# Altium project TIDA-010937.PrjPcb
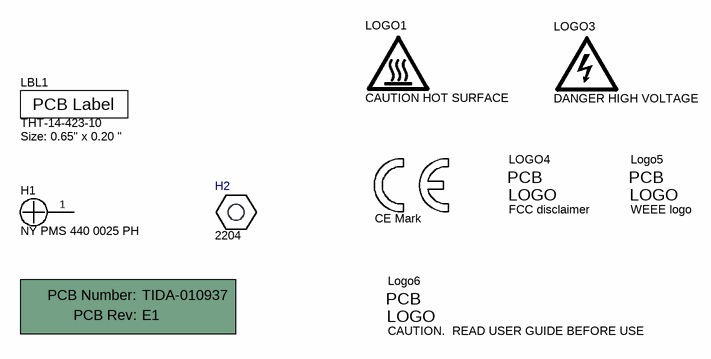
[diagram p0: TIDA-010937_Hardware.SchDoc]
TID: N/A; TechSupport: http://www.ti.com/support; SCH_Rev: E1; PRJ_Title: TMCS1123 isolated current sensing; PRJ_Number: TIDA-010937; PRJ_Engineer: Yufeng/Martin; PRJ_Customer: Public Release; PCB_Rev: E1; PCB_Layout: Yufeng; CopyrightYear: 2023
2 sheets, 91 parts. Net scope: flat (ports and power ports of the same name join across sheets).
Board file: TIDA-010937_PCB.PcbDoc
Sheets:
  TIDA-010937_Hardware.SchDoc
  TIDA-010937_SCH.SchDoc

## Sheet TIDA-010937_Hardware.SchDoc
size 431 x 279 mm; Date: Not shown in title block; ApprovedBy: Not shown in title block; CheckedBy: Not shown in title block; Author: Not shown in title block; CompanyName: Not shown in title block; Engineer: Not shown in title block; Organization: Not shown in title block; Address1: Not shown in title block; Address2: Not shown in title block; Address3: Not shown in title block; Address4: Not shown in title block; DocumentNumber: 3; Revision: Use project parameter SCH_Rev; SheetNumber: 2; SheetTotal: 3; PageSetup: Record=PageOptions¦CenterHorizontal=True¦CenterVertical=True¦PrintScale=1.00¦XCorrection=1.00¦YCorrection=1.00¦PrintKind=0¦BorderSize=5000000¦LeftOffset=0¦BottomOffset=0¦Orientation=2¦PaperLength=1000¦PaperWidth=1000¦Scale=100¦PaperSource=15¦PrintQuality=600¦MediaType=1¦DitherType=10¦PaperKind=Letter¦PrintScaleMode=1

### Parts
!PCB1  Printed Circuit Board  (value not drawn)  (mechanical)
H1  NY PMS 440 0025 PH  [NY PMS 440 0025 PH]
H2  2204  [Keystone_2204]
LBL1  THT-14-423-10  Note: Size: 0.65" x 0.20 "  [Label_650x200]
LOGO1  CAUTION HOT SURFACE  [IEC_HotSurface_Medium]  (no BOM)
Logo2  CE Mark  [CE_Mark_5mm]  (no BOM)
LOGO3  DANGER HIGH VOLTAGE  [IEC_HighVoltage_Medium]  (no BOM)
LOGO4  FCC disclaimer  [FCC_disclaimer]  (no BOM)
Logo5  WEEE logo  [WEEE_Minimum]  (no BOM)
Logo6  CAUTION.  READ USER GUIDE BEFORE USE  [IEC_Caution_Small]  (no BOM)

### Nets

Not connected (* = marked no-connect by the designer): H1 1

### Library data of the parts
!PCB1 = CMP-0003618-2: Manufacturer: Any; PartNumber: TIDA-010937
H1 = CMP-0003617-1: Machine Screw, Round, #4-40 x 1/4, Nylon, Philips panhead; Manufacturer: B&F Fastener Supply; CompType: Hardware
H2 = CMP-0003917-1: Manufacturer: Keystone; CompType: Standoff
LBL1 = CMP-0003625-1: Thermal Transfer Printable Labels, 0.650" W x 0.200" H - 10,000 per roll; Manufacturer: Brady; CompType: Label
LOGO1 = CMP-0074837-1: IEC 61010-1 Hot Surface Warning; SymbolCreator: a0412235
Logo2 = CMP-0074844-1: SymbolCreator: a0412235
LOGO3 = CMP-0074835-1: IEC 61010-1 High Voltage Warning; SymbolCreator: a0412235
LOGO4 = CMP-0074847-1: FCC_disclaimer; Library Reference: Logo
Logo5 = CMP-0074769-1
Logo6 = CMP-0074836-1: IEC 61010-1 Caution Warning; SymbolCreator: a0412235; Lib Reference: IEC_Caution

## Sheet TIDA-010937_SCH.SchDoc
size 431 x 279 mm; Date: Not shown in title block; ApprovedBy: Not shown in title block; CheckedBy: Not shown in title block; Author: Not shown in title block; CompanyName: Not shown in title block; Engineer: Not shown in title block; Organization: Not shown in title block; Address1: Not shown in title block; Address2: Not shown in title block; Address3: Not shown in title block; Address4: Not shown in title block; DocumentNumber: 2; Revision: Use project parameter SCH_Rev; SheetNumber: 2; SheetTotal: 2; PageSetup: Record=PageOptions¦CenterHorizontal=True¦CenterVertical=True¦PrintScale=1.00¦XCorrection=1.00¦YCorrection=1.00¦PrintKind=0¦BorderSize=5000000¦LeftOffset=0¦BottomOffset=0¦Orientation=2¦PaperLength=1000¦PaperWidth=1000¦Scale=100¦PaperSource=15¦PrintQuality=600¦MediaType=1¦DitherType=10¦PaperKind=Letter¦PrintScaleMode=1
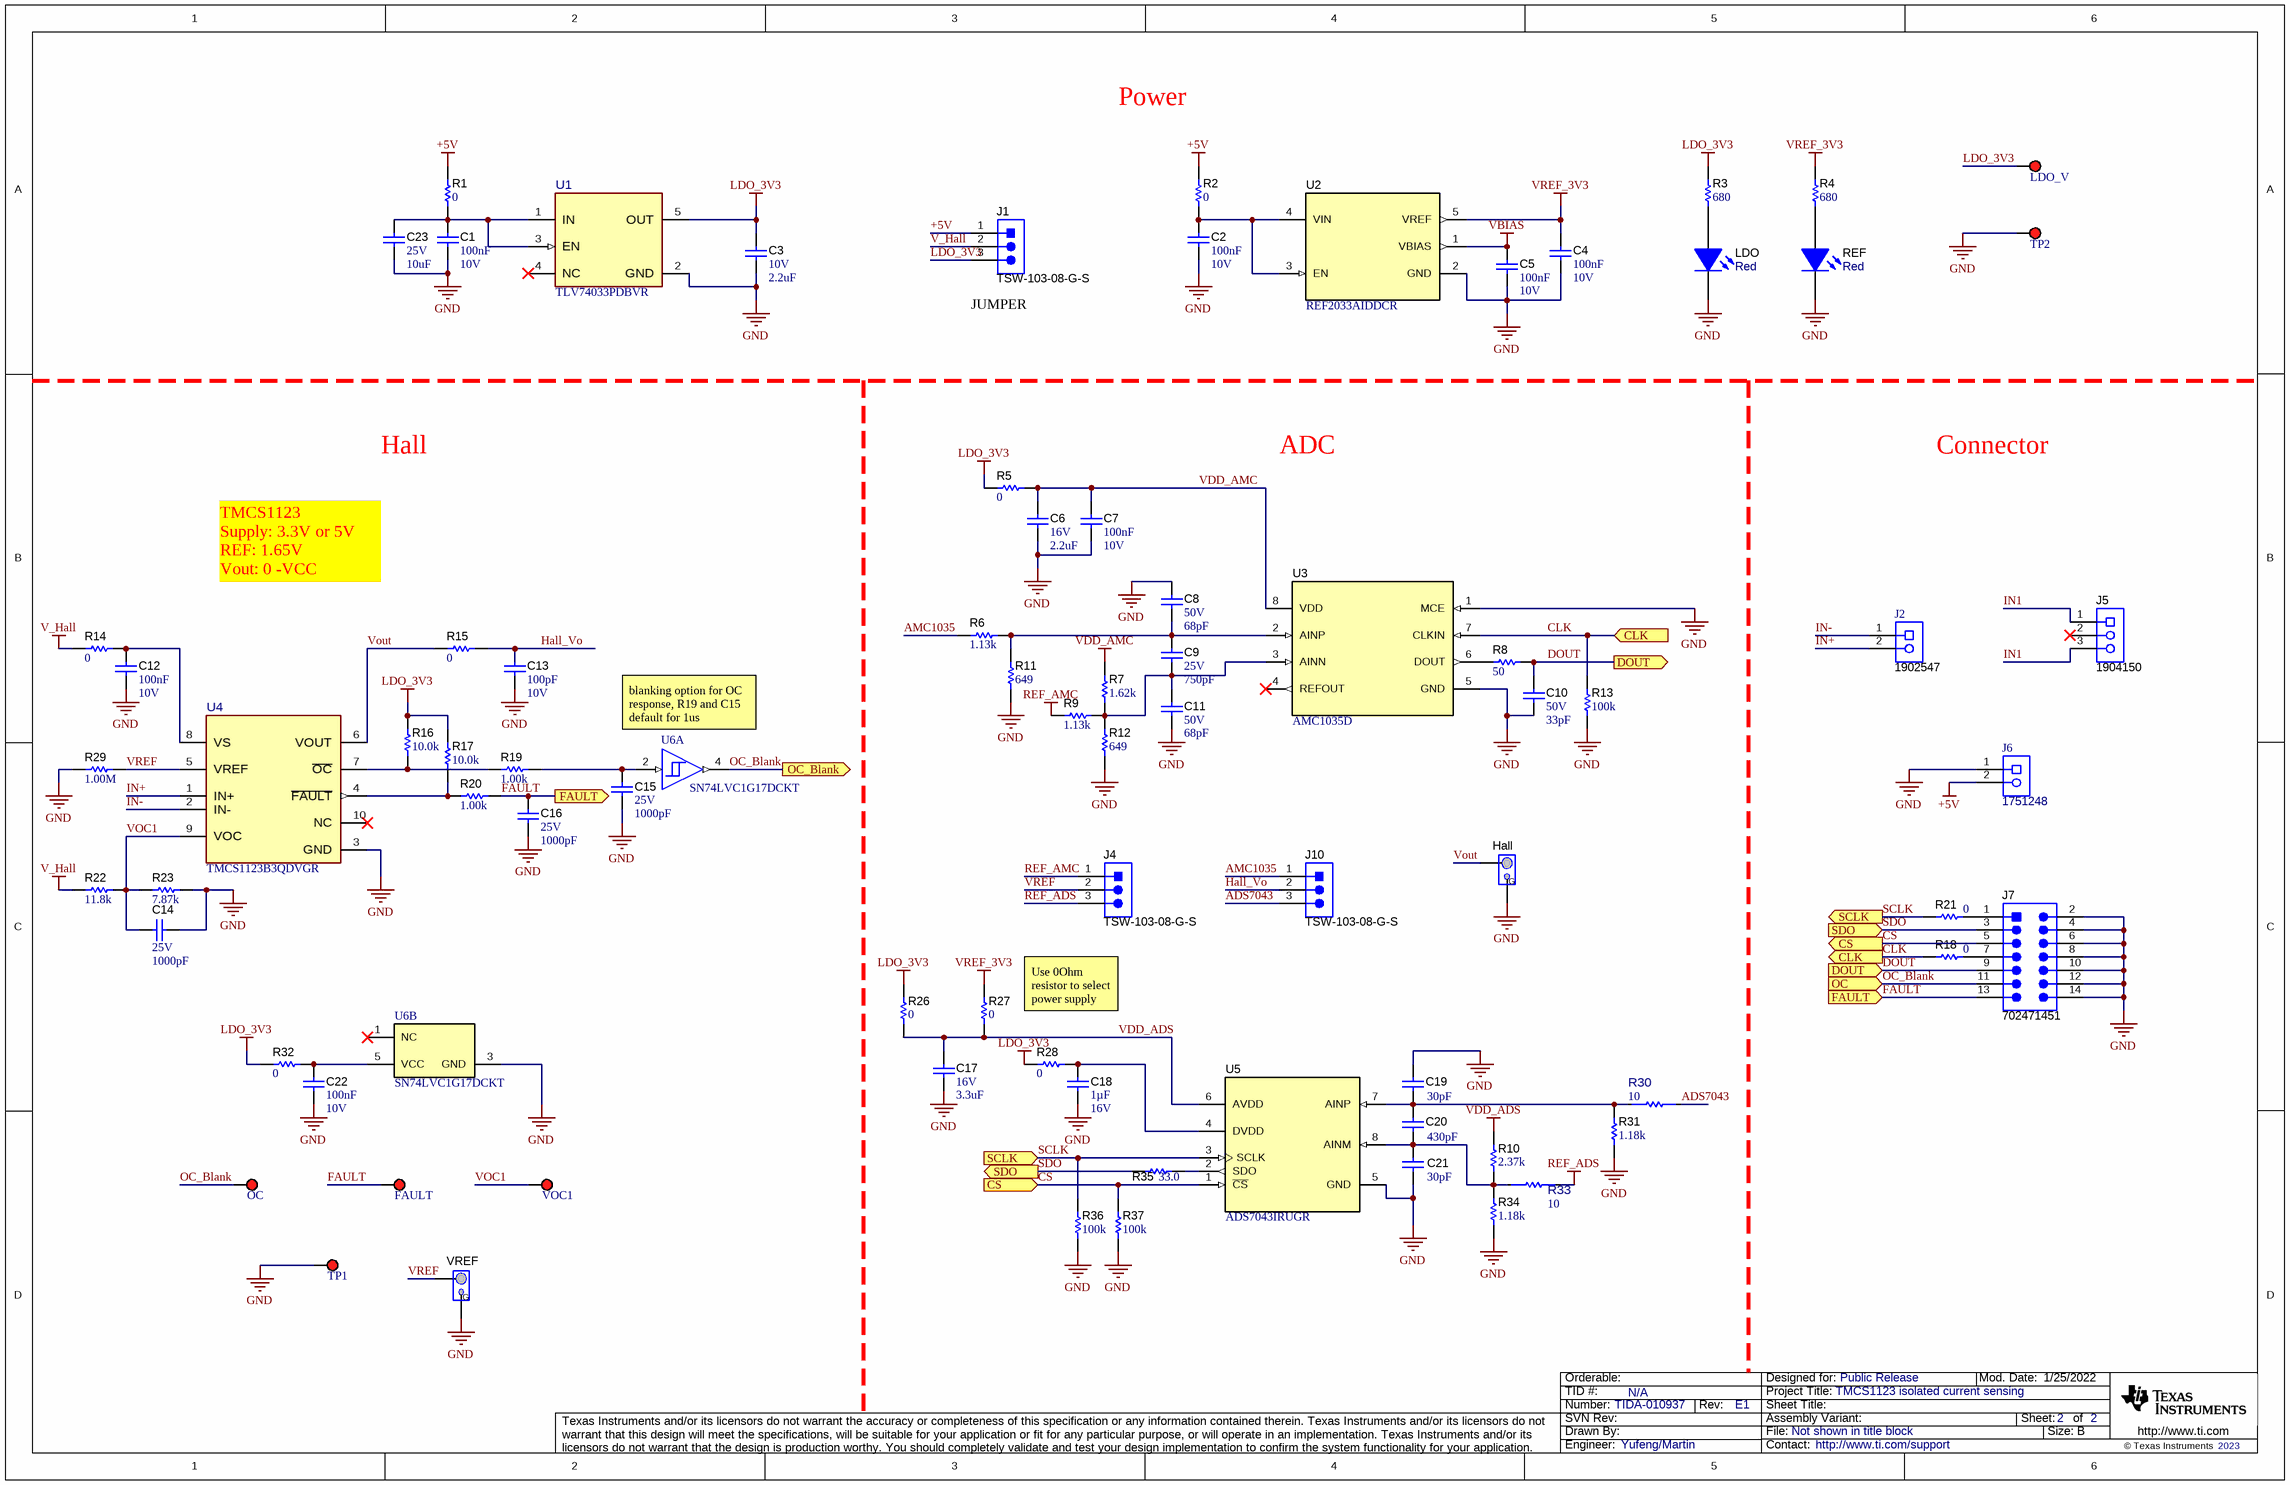
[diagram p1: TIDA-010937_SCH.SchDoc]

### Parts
C1  Cap_F: 100nF  VDC_V: 10V  [0603]  (hidden comment: C0603C104K8RACTU)
C2  Cap_F: 100nF  VDC_V: 10V  [0603]  (hidden comment: C0603C104K8RACTU)
C3  VDC_V: 10V  ValueDisplayed: 2.2uF  [0603]  (hidden comment: LMK107BJ225KA-T)
C4  Cap_F: 100nF  VDC_V: 10V  [0603]  (hidden comment: C0603C104K8RACTU)
C5  Cap_F: 100nF  VDC_V: 10V  [0603]  (hidden comment: C0603C104K8RACTU)
C6  VDC_V: 16V  ValueDisplayed: 2.2uF  [0603]  (hidden comment: GRM188R61C225KE15D)
C7  Cap_F: 100nF  VDC_V: 10V  [0603]  (hidden comment: C0603C104K8RACTU)
C8  VDC_V: 50V  ValueDisplayed: 68pF  [0603]  (hidden comment: C0603C680J5GACTU)
C9  VDC_V: 25V  ValueDisplayed: 750pF  [0603]  (hidden comment: GRM1885C1E751JA01D)
C10  VDC_V: 50V  ValueDisplayed: 33pF  [0603]  (hidden comment: GRM1885C1H330JA01D)
C11  VDC_V: 50V  ValueDisplayed: 68pF  [0603]  (hidden comment: C0603C680J5GACTU)
C12  Cap_F: 100nF  VDC_V: 10V  [0603]  (hidden comment: C0603C104K8RACTU)
C13  Cap_F: 100pF  VDC_V: 10V  [0603]  (hidden comment: 0603ZC101KAT2A)
C14  VDC_V: 25V  ValueDisplayed: 1000pF  [0603]  (hidden comment: GRM1885C1E681JA01D)
C15  VDC_V: 25V  ValueDisplayed: 1000pF  [0603]  (hidden comment: GRM1885C1E681JA01D)
C16  VDC_V: 25V  ValueDisplayed: 1000pF  [0603]  (hidden comment: GRM1885C1E681JA01D)
C17  VDC_V: 16V  ValueDisplayed: 3.3uF  [0603]  (hidden comment: C1608X6S1C335K080AC)
C18  Cap_F: 1µF  VDC_V: 16V  [0603]  (hidden comment: EMK107B7105KAHT)
C19  ValueDisplayed: 30pF  [0603]  (hidden comment: 06035A300JAT2A)
C20  ValueDisplayed: 430pF  [0603]  (hidden comment: GRM1885C1H431JA01D)
C21  ValueDisplayed: 30pF  [0603]  (hidden comment: 06035A300JAT2A)
C22  Cap_F: 100nF  VDC_V: 10V  [0603]  (hidden comment: C0603C104K8RACTU)
C23  VDC_V: 25V  ValueDisplayed: 10uF  [0805_HV]  (hidden comment: TMK212BBJ106MG-T)
FAULT  5000  [Keystone5000]  (value not drawn)
Hall  (no value)  [TESTPOINT_PIGTAIL]  (no BOM)
J1  TSW-103-08-G-S  [Samtec_TSW-103-08-x-S]
J2  1902547  [Phoenix_1902547]
J4  TSW-103-08-G-S  [Samtec_TSW-103-08-x-S]
J5  1904150  [Phoenix_1904150]
J6  1751248  [CONN_1751248]
J7  702471451  [Molex_0702471451]
J10  TSW-103-08-G-S  [Samtec_TSW-103-08-x-S]
LDO  value Red  [WL-SMCW_RED_0805]  (hidden comment: 150080SS75000)
LDO_V  5000  [Keystone5000]  (value not drawn)
OC  5000  [Keystone5000]  (value not drawn)
R1  ValueDisplayed: 0  [0603]  (hidden comment: RC0603JR-070RL)
R2  ValueDisplayed: 0  [0603]  (hidden comment: RC0603JR-070RL)
R3  ValueDisplayed: 680  [0603]  (hidden comment: RC0603JR-07680RL)
R4  ValueDisplayed: 680  [0603]  (hidden comment: RC0603JR-07680RL)
R5  ValueDisplayed: 0  [0603]  (hidden comment: RC0603JR-070RL)
R6  ValueDisplayed: 1.13k  [0603]  (hidden comment: RT0603BRD071K13L)
R7  ValueDisplayed: 1.62k  [0603]  (hidden comment: CPF0603B1K62E)
R8  ValueDisplayed: 50  [0603]  (hidden comment: CRCW060350R0FKEA)
R9  ValueDisplayed: 1.13k  [0603]  (hidden comment: RT0603BRD071K13L)
R10  ValueDisplayed: 2.37k  [0603]  (hidden comment: RG1608P-2371-B-T5)
R11  ValueDisplayed: 649  [0603]  (hidden comment: RT0603BRD07649RL)
R12  ValueDisplayed: 649  [0603]  (hidden comment: RT0603BRD07649RL)
R13  ValueDisplayed: 100k  [0603]  (hidden comment: CRCW0603100KJNEA)
R14  ValueDisplayed: 0  [0603]  (hidden comment: RC0603JR-070RL)
R15  ValueDisplayed: 0  [0603]  (hidden comment: RC0603JR-070RL)
R16  ValueDisplayed: 10.0k  [0603]  (hidden comment: M55342K12B10E0T)
R17  ValueDisplayed: 10.0k  [0603]  (hidden comment: M55342K12B10E0T)
R18  ValueDisplayed: 0  [0603]  (hidden comment: RC0603JR-070RL)
R19  ValueDisplayed: 1.00k  [0603]  (hidden comment: RC0603FR-0710RL)
R20  ValueDisplayed: 1.00k  [0603]  (hidden comment: RC0603FR-0710RL)
R21  ValueDisplayed: 0  [0603]  (hidden comment: RC0603JR-070RL)
R22  ValueDisplayed: 11.8k  [0603]  (hidden comment: RC0603FR-0711K8L)
R23  ValueDisplayed: 7.87k  [0603]  (hidden comment: RC0603FR-077K87L)
R26  ValueDisplayed: 0  [0603]  (hidden comment: RC0603JR-070RL)
R27  ValueDisplayed: 0  [0603]  (hidden comment: RC0603JR-070RL)
R28  ValueDisplayed: 0  [0603]  (hidden comment: RC0603JR-070RL)
R29  ValueDisplayed: 1.00M  [0603]  (hidden comment: MCT06030C1004FP500)
R30  value 10  [FP-ESR03EZPF10R0_0603-MFG]  (hidden comment: ESR03EZPF10R0)
R31  ValueDisplayed: 1.18k  [0603]  (hidden comment: RT0603BRD071K18L)
R32  ValueDisplayed: 0  [0603]  (hidden comment: RC0603JR-070RL)
R33  value 10  [FP-ESR03EZPF10R0_0603-MFG]  (hidden comment: ESR03EZPF10R0)
R34  ValueDisplayed: 1.18k  [0603]  (hidden comment: RT0603BRD071K18L)
R35  ValueDisplayed: 33.0  [0603]  (hidden comment: RC0603FR-0733RL)
R36  ValueDisplayed: 100k  [0603]  (hidden comment: CRCW0603100KJNEA)
R37  ValueDisplayed: 100k  [0603]  (hidden comment: CRCW0603100KJNEA)
REF  value Red  [WL-SMCW_RED_0805]  (hidden comment: 150080SS75000)
TP1  5000  [Keystone5000]  (value not drawn)
TP2  5000  [Keystone5000]  (value not drawn)
U1  TLV74033PDBVR  [DBV0005A-MFG]
U2  REF2033AIDDCR  [DDC0005A_N]
U3  AMC1035D  [D0008A_N]
U4  TMCS1123B3QDVGR  [DVG0010A-MFG]
U5  ADS7043IRUGR  [RUG0008A]
U6  SN74LVC1G17DCKT  [DCK0005A_N]  (parts A,B of 2)
VOC1  5000  [Keystone5000]  (value not drawn)
VREF  (no value)  [TESTPOINT_PIGTAIL]  (no BOM)

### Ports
CLK (in), CLK (out), CS (in), CS (out), DOUT (in), DOUT (out), FAULT (in), FAULT (out), OC (in), OC_Blank (out), SCLK (in), SCLK (out), SDO (in), SDO (out)

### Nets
+5V: J1.1 J6.2 R1.1 R2.1
GND: C1.2 C2.2 C3.2 C4.2 C5.2 C6.1 C7.2 C8.1 C10.2 C11.2 C12.2 C13.2 C14.2 C15.2 C16.2 C17.1 C18.1 C19.1 C21.2 C22.2 C23.2 Hall.2 J6.1 J7.2 J7.4 J7.6 J7.8 J7.10 J7.12 J7.14 LDO.1(K) R11.1 R12.1 R13.1 R23.2 R29.1 R31.1 R34.1 R36.1 R37.1 REF.1(K) TP1.1 TP2.1 U1.2(GND) U2.2(GND) U3.1(MCE) U3.5(GND) U4.3(GND) U5.5(GND) U6.3(GND) VREF.2
LDO_3V3: C3.1 J1.3 LDO_V.1 R3.2 R5.1 R16.2 R17.2 R26.1 R28.2 R32.2 U1.5(OUT)
REF_ADS: J4.3 R33.2
REF_AMC: J4.1 R9.1
V_Hall: J1.2 R14.2 R22.1
VBIAS: C5.1 U2.1(VBIAS)
VDD_ADS: C17.2 R10.2 R26.2 R27.2 U5.6(AVDD)
VDD_AMC: C6.2 C7.1 R5.2 R7.2 U3.8(VDD)
VREF_3V3: C4.1 R4.2 R27.1 U2.5(VREF)
ADS7043: J10.3 R30.2
AMC1035: J10.1 R6.1
CLK: R13.2 R18.1 U3.7(CLKIN) ; port CLK
CS: J7.5 R37.2 U5.1(~{CS}) ; port CS
DOUT: C10.1 J7.9 R8.2 ; port DOUT
FAULT: C16.1 FAULT.1 J7.13 R20.2 ; port FAULT
Hall_Vo: C13.1 J10.2 R15.2
IN1: J5.1 J5.3
IN+: J2.2 U4.1(IN+)
IN-: J2.1 U4.2(IN-)
OC_Blank: J7.11 OC.1 U6.4(Y) ; port OC_Blank, port OC
SCLK: R21.1 R36.2 U5.3(SCLK) ; port SCLK
SDO: J7.3 R35.1 ; port SDO
VOC1: C14.1 R22.2 R23.1 U4.9(VOC) VOC1.1
Vout: Hall.1 R15.1 U4.6(VOUT)
VREF: J4.2 R29.2 U4.5(VREF) VREF.1
NetC1_1: C1.1 C23.1 R1.2 U1.1(IN) U1.3(EN)
NetC2_1: C2.1 R2.2 U2.3(EN) U2.4(VIN)
NetC8_2: C8.2 C9.1 R6.2 R11.2 U3.2(AINP)
NetC9_2: C9.2 C11.1 R7.1 R9.2 R12.2 U3.3(AINN)
NetC12_1: C12.1 R14.1 U4.8(VS)
NetC15_1: C15.1 R19.2 U6.2(A)
NetC18_2: C18.2 R28.1 U5.4(DVDD)
NetC19_2: C19.2 C20.1 R30.1 R31.2 U5.7(AINP)
NetC20_2: C20.2 C21.1 R10.1 R33.1 R34.2 U5.8(AINM)
NetC22_1: C22.1 R32.1 U6.5(VCC)
NetJ7_1: J7.1 R21.2
NetJ7_7: J7.7 R18.2
NetLDO_2: LDO.2(A) R3.1
NetR4_1: R4.1 REF.2(A)
NetR8_1: R8.1 U3.6(DOUT)
NetR16_1: R16.1 R19.1 U4.7(~{OC})
NetR17_1: R17.1 R20.1 U4.4(~{FAULT})
NetR35_2: R35.2 U5.2(SDO)

Not connected (* = marked no-connect by the designer): J5 2*; U1 4(NC)*; U3 4(REFOUT)*; U4 10(NC)*; U6 1(NC)*

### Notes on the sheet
- Power
- (near J1) JUMPER
- Hall
- ADC
- Connector
- TMCS1123
  Supply: 3.3V or 5V
  REF: 1.65V
  Vout: 0 -VCC
- blanking option for OC response, R19 and C15 default for 1us
- Use 0Ohm resistor to select power supply

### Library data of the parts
C1 C2 C4 C5 C7 C12 C22 = CMP-0006862-3: CAP, CERM, 0.1 uF, 10 V, +/- 10%, X7R, 0603; Manufacturer: Kemet; TaMin_C: -55°C; Polarized: N; SizeAreaWB_mm2: 4.68; Value1: Unknown; U/M: EA; Value: 0.1uF; TaMax_C: 125°C; SizeZ_mm: 1; SizeX_mm: 1.6; SizeY_mm: 0.8; SizeArea_mm2: 1.28; AEC Category: Q200
C3 = CMP-0007506-5: CAP, CERM, 2.2 uF, 10 V, +/- 10%, X5R, 0603; Manufacturer: Taiyo Yuden; TaMin_C: -55°C; Polarized: N; SizeAreaWB_mm2: 4.68; Value1: Unknown; U/M: EA; Value: 2.2uF; TaMax_C: 85°C; SizeZ_mm: 1; SizeX_mm: 1.6; SizeY_mm: 0.8; SizeArea_mm2: 1.28; Cap_F: 2.2µF; AEC Category: Q200
C6 = CMP-0007339-4: CAP, CERM, 2.2 uF, 16 V, +/- 10%, X5R, 0603; Manufacturer: MuRata; TaMin_C: -55°C; Polarized: N; SizeAreaWB_mm2: 4.68; Value1: Unknown; U/M: EA; Value: 2.2uF; TaMax_C: 85°C; SizeZ_mm: 1; SizeX_mm: 1.6; SizeY_mm: 0.8; SizeArea_mm2: 1.28; Cap_F: 2.2µF; AEC Category: Q200
C8 C11 = CMP-0006958-4: CAP, CERM, 68 pF, 50 V, +/- 5%, C0G/NP0, 0603; Manufacturer: Kemet; TaMin_C: -55°C; Polarized: N; SizeAreaWB_mm2: 4.68; Value1: Unknown; U/M: EA; Value: 68pF; TaMax_C: 125°C; SizeZ_mm: 1; SizeX_mm: 1.6; SizeY_mm: 0.8; SizeArea_mm2: 1.28; AEC Category: Q200
C9 = CMP-0007167-4: CAP, CERM, 750 pF, 25 V, +/- 5%, C0G/NP0, 0603; Manufacturer: MuRata; TaMin_C: -55°C; Polarized: N; SizeAreaWB_mm2: 4.68; Value1: Unknown; U/M: EA; Value: 750pF; TaMax_C: 125°C; SizeZ_mm: 1; SizeX_mm: 1.6; SizeY_mm: 0.8; SizeArea_mm2: 1.28; AEC Category: Q200
C10 = CMP-0007208-2: CAP, CERM, 33 pF, 50 V, +/- 5%, C0G/NP0, 0603; Manufacturer: MuRata; TaMin_C: -55°C; Polarized: N; SizeAreaWB_mm2: 4.68; Value1: Unknown; U/M: EA; Value: 33pF; TaMax_C: 125°C; SizeZ_mm: 1; SizeX_mm: 1.6; SizeY_mm: 0.8; SizeArea_mm2: 1.28; AEC Category: Q200
C13 = CMP-0006812-1: CAP, CERM, 100 pF, 10 V, +/- 10%, X7R, 0603; Manufacturer: AVX; TaMin_C: -55°C; Polarized: N; SizeAreaWB_mm2: 4.68; Value1: Unknown; U/M: EA; Value: 100pF; TaMax_C: 125°C; SizeZ_mm: 1; SizeX_mm: 1.6; SizeY_mm: 0.8; SizeArea_mm2: 1.28; AEC Category: Q200
C14-C16 = CMP-0080092-1: CAP, CERM, 1000 pF, 25 V,+/- 1%, C0G/NP0, 0603; PartNumber: C0603C102F3GACTU; Manufacturer: Kemet; Cap_F: 1nF; SizeAreaWB_mm2: 4.68; SizeArea_mm2: 1.28; AEC Qualified: N; AEC Category: Q200; Value: 1000pF; TaMax_C: 125°C; SizeZ_mm: 1; Green_REACh: Passed; TaMin_C: -55°C; SizeY_mm: 0.8; Green_Lifecycle: Active; U/M: EA; SizeX_mm: 1.6
C17 = CMP-0007027-4: CAP, CERM, 3.3 uF, 16 V, +/- 10%, X6S, 0603; Manufacturer: TDK; TaMin_C: -55°C; ESR_ohm: 4.796m; Polarized: N; SizeAreaWB_mm2: 4.68; Value1: 0.004796 ohm; U/M: EA; Value: 3.3uF; TaMax_C: 105°C; SizeZ_mm: 1; SizeX_mm: 1.6; SizeY_mm: 0.8; SizeArea_mm2: 1.28; Cap_F: 3.3µF; IRMS_A: 2.3752A; AEC Category: Q200
C18 = CMP-0080104-1: CAP, CERM, 1 µF, 16 V,+/- 10%, X7R, AEC-Q200 Grade 1, 0603; Manufacturer: Taiyo Yuden; SizeAreaWB_mm2: 4.68; SizeArea_mm2: 1.28; AEC Qualified: Y; AEC Category: Q200; Value: 1uF; TaMax_C: 125°C; SizeZ_mm: 1; Polarized: N; TaMin_C: -55°C; SizeY_mm: 0.8; U/M: EA; SizeX_mm: 1.6
C19 C21 = CMP-0006782-2: CAP, CERM, 30 pF, 50 V, +/- 5%, C0G/NP0, 0603; Manufacturer: AVX; TaMin_C: -55°C; ESR_ohm: 0.232; Polarized: N; SizeAreaWB_mm2: 4.68; Value1: 0.232 ohm; U/M: EA; Value: 30pF; TaMax_C: 125°C; SizeZ_mm: 1; SizeX_mm: 1.6; SizeY_mm: 0.8; Value2: 50V; SizeArea_mm2: 1.28; AEC Category: Q200
C20 = CMP-0007218-3: CAP, CERM, 430 pF, 50 V, +/- 5%, C0G/NP0, 0603; Manufacturer: MuRata; TaMin_C: -55°C; Polarized: N; SizeAreaWB_mm2: 4.68; Value1: Unknown; U/M: EA; Value: 430pF; TaMax_C: 125°C; SizeZ_mm: 1; SizeX_mm: 1.6; SizeY_mm: 0.8; Value2: 50V; SizeArea_mm2: 1.28; AEC Category: Q200
C23 = CMP-0008415-2: CAP, CERM, 10 uF, 25 V, +/- 20%, X5R, 0805; Manufacturer: Taiyo Yuden; TaMin_C: -55°C; Polarized: N; SizeAreaWB_mm2: 6.75; Value1: Unknown; U/M: EA; Value: 10uF; TaMax_C: 85°C; SizeZ_mm: 1.45; SizeX_mm: 2; SizeY_mm: 1.25; Cap_Case: 0805; SizeArea_mm2: 2.5; Cap_F: 10µF; AEC Category: Q200
FAULT LDO_V OC TP1 TP2 VOC1 = CMP-0055137-1: Test Point, Miniature, Red, TH; Manufacturer: Keystone; CNHeader: FALSE; Green_Lifecycle: Active; Green_REACh: Passed; ContactFinish: Silver; CT: TRUE
Hall VREF = CMP-0003907-1: PIGTAIL; Manufacturer: Texas Instruments; CompType: Test Point
J1 J4 J10 = CMP-0079327-1: Header, 2.54mm, 3x1, Gold, TH; Manufacturer: Samtec; Pitch_mm: 2.54; Gender: Male; Cert_UL: Y; Shrouded: N; Row_Count: 1
J2 = CMP-0055527-1: Terminal Block, 9.52mm, 2x1, R/A, TH; Manufacturer: Phoenix Contact; Cert_VDE: Y; CNHeader: FALSE; Current_A: 32A; Gender: Female; Voltage_V: 1kV; Row_Count: 1; Pitch_mm: 9.52; CT: TRUE
J5 = CMP-0055528-1: Terminal Block, 9.52mm, 3x1, R/A, TH; Manufacturer: Phoenix Contact; Cert_VDE: Y; CNHeader: FALSE; Current_A: 32A; Gender: Female; Voltage_V: 1kV; Row_Count: 1; Pitch_mm: 9.52; CT: TRUE
J6 = CMP-0055473-1: Conn Term Block, 2POS, 3.5mm, TH; Manufacturer: Phoenix Contact; CNHeader: FALSE; Green_Lifecycle: Not Set; Green_REACh: Incomplete; CompType: Terminal Block; CT: TRUE
J7 = CMP-0055272-2: Header(shrouded), 2.54mm, 7x2, R/A, Gold, TH; Manufacturer: Molex; Current_A: 2.5A; Shrouded: Y; Gender: Male; Voltage_V: 250V; Row_Count: 2; RowSpacing_mm: 2.54
LDO REF = CMP-0002951-3: LED, Red, SMD; Manufacturer: Wurth Elektronik; Vf_V: 1.9V; Io_A: 30mA; Vr_V: 5V; Ir_A: 25µA; Tjmax_C: 85°C; Power_TotalModule: 72mW; Value1: 0.072W; Angle: 140
R1 R2 R5 R14 R15 R18 R21 R26-R28 R32 = CMP-0025885-5: RES, 0, 5%, 0.1 W, 0603; Manufacturer: Yageo; Power_W: 100mW; TempCo: 200 ppm/C; Value_Code: 0000; Value: 0; EIA_Code: E24; SizeX_mm: 1.6; SizeZ_mm: 1; Value2: 0.1W; SizeArea_mm2: 1.28; AEC Qualified: N; VDC_V: 75V; AEC Category: Q200; SizeY_mm: 0.8; SizeAreaWB_mm2: 4.68
R3 R4 = CMP-0025936-5: RES, 680, 5%, 0.1 W, 0603; Manufacturer: Yageo; Power_W: 100mW; TempCo: 100 ppm/C; Value_Code: 680R; Value: 680; EIA_Code: E24; SizeX_mm: 1.6; SizeY_mm: 0.8; SizeZ_mm: 1; Value2: 0.1W; SizeArea_mm2: 1.28; AEC Qualified: N; VDC_V: 75V; AEC Category: Q200; SizeAreaWB_mm2: 4.68
R6 R9 = CMP-0023870-3: RES, 1.13 k, 0.1%, 0.1 W, 0603; Manufacturer: Yageo America; Power_W: 100mW; TempCo: 25 ppm/C; Value_Code: 1k13; U/M: EA; Value: 1.13k; EIA_Code: E192; SizeX_mm: 1.6; SizeY_mm: 0.8; SizeZ_mm: 1; Value2: 0.1W; SizeArea_mm2: 1.28; VDC_V: 75V; AEC Category: Q200
R7 = CMP-0023347-3: RES, 1.62 k, 0.1%, 0.063 W, 0603; Manufacturer: TE Connectivity; Power_W: 63mW; TempCo: 25 ppm/C; Value_Code: 1k62; U/M: EA; Value: 1.62k; EIA_Code: E192; SizeX_mm: 1.6; SizeY_mm: 0.8; SizeZ_mm: 1; Value2: 0.063W; SizeArea_mm2: 1.28; VDC_V: 50V; AEC Category: Q200
R8 = CMP-0022479-2: RES, 50, 1%, 0.1 W, 0603; Manufacturer: Vishay-Dale; Power_W: 100mW; TempCo: 100 ppm/C; Value_Code: 50R0; U/M: EA; Value: 50; SizeX_mm: 1.6; SizeY_mm: 0.8; SizeZ_mm: 1; Value2: 0.1W; SizeArea_mm2: 1.28; VDC_V: 75V; AEC Category: Q200
R10 = CMP-0023481-1: RES, 2.37 k, 0.1%, 0.1 W, 0603; Manufacturer: Susumu Co Ltd; Power_W: 100mW; TempCo: 25 ppm/C; Value_Code: 2k37; U/M: EA; Value: 2.37k; EIA_Code: E192; SizeX_mm: 1.6; SizeY_mm: 0.8; SizeZ_mm: 1; Value2: 0.1W; SizeArea_mm2: 1.28; VDC_V: 75V; AEC Category: Q200
R11 R12 = CMP-0024403-3: RES, 649, 0.1%, 0.1 W, 0603; Manufacturer: Yageo America; Power_W: 100mW; TempCo: 25 ppm/C; Value_Code: 649R; U/M: EA; Value: 649; EIA_Code: E192; SizeX_mm: 1.6; SizeY_mm: 0.8; SizeZ_mm: 1; Value2: 0.1W; SizeArea_mm2: 1.28; AEC Qualified: N; VDC_V: 75V; AEC Category: Q200
R13 R36 R37 = CMP-0025698-4: RES, 100 k, 5%, 0.1 W, AEC-Q200 Grade 0, 0603; Manufacturer: Vishay-Dale; Power_W: 100mW; TempCo: 200 ppm/C; Value: 100k; EIA_Code: E24; SizeX_mm: 1.6; SizeY_mm: 0.8; SizeZ_mm: 1; Value2: 0.1W; SizeArea_mm2: 1.28; AEC Qualified: Y; VDC_V: 75V; AEC Category: Q200; AEC Grade: 0
R16 R17 = CMP-0080488-1: RES, 10.0 k, 1%, 0.1 W, 0603; Manufacturer: TT Electronics/IRC; Power_W: 100mW; TempCo: 100 ppm/C; SizeAreaWB_mm2: 4.68; Value_Code: 10k0; Value: 10.0k; EIA_Code: E96; Res_ohm: 10k; SizeX_mm: 1.6; SizeY_mm: 0.8; SizeZ_mm: 1; Value2: 0.1W; SizeArea_mm2: 1.28; AEC Qualified: N; AEC Category: Q200
R19 R20 = CMP-0024852-1: RES, 1.00 k, 0.5%, 0.1 W, 0603; Manufacturer: Yageo America; PartNumber: RT0603DRE071KL; Power_W: 100mW; TempCo: 50 ppm/C; Value_Code: 1k00; U/M: EA; Value: 1.00k; EIA_Code: E192; Res_ohm: 1k; SizeX_mm: 1.6; SizeY_mm: 0.8; SizeZ_mm: 1; Value2: 0.1W; SizeArea_mm2: 1.28; VDC_V: 75V; AEC Category: Q200
R22 = CMP-0022762-5: RES, 11.8 k, 1%, 0.1 W, 0603; Manufacturer: Yageo; Power_W: 100mW; TempCo: 100 ppm/C; Value_Code: 11k8; Value: 11.8k; EIA_Code: E96; SizeX_mm: 1.6; SizeY_mm: 0.8; SizeZ_mm: 1; Value2: 0.1W; SizeArea_mm2: 1.28; AEC Qualified: N; VDC_V: 75V; AEC Category: Q200; SizeAreaWB_mm2: 4.68
R23 = CMP-0023281-5: RES, 7.87 k, 1%, 0.1 W, 0603; Manufacturer: Yageo; Power_W: 100mW; TempCo: 100 ppm/C; Value_Code: 7k87; Value: 7.87k; EIA_Code: E96; SizeX_mm: 1.6; SizeY_mm: 0.8; SizeZ_mm: 1; Value2: 0.1W; SizeArea_mm2: 1.28; AEC Qualified: N; VDC_V: 75V; AEC Category: Q200; SizeAreaWB_mm2: 4.68
R29 = CMP-0022731-1: RES, 1.00 M, 1%, 0.125 W, 0603; Manufacturer: Vishay/Beyschlag; Power_W: 125mW; TempCo: 50 ppm/C; Value_Code: 1M00; U/M: EA; Value: 1.00Meg; EIA_Code: E96; Res_ohm: 1M; SizeX_mm: 1.6; SizeY_mm: 0.8; SizeZ_mm: 1; Value2: 0.125W; SizeArea_mm2: 1.28; AEC Qualified: N; VDC_V: 75V; AEC Category: Q200
R30 R33 = CMP-0094841-1: 10 Ohms ±1% 0.25W, 1/4W Chip Resistor 0603 (1608 Metric) Automotive AEC-Q200, Pulse Withstanding Thick Film; Manufacturer: ROHM; AEC Qualified: Yes; SizeZ_mm: 0.55mm; TempCo: 100ppm/°C; AEC Grade: Grade 0; Power_W: 250mW; VDC_V: 150V
R31 R34 = CMP-0023874-3: RES, 1.18 k, 0.1%, 0.1 W, 0603; Manufacturer: Yageo America; Power_W: 100mW; TempCo: 25 ppm/C; Value_Code: 1k18; U/M: EA; Value: 1.18k; EIA_Code: E192; SizeX_mm: 1.6; SizeY_mm: 0.8; SizeZ_mm: 1; Value2: 0.1W; SizeArea_mm2: 1.28; VDC_V: 75V; AEC Category: Q200
R35 = CMP-0023039-4: RES, 33.0, 1%, 0.1 W, 0603; Manufacturer: Yageo; Power_W: 100mW; TempCo: 100 ppm/C; Value_Code: 33R0; Value: 33.0; Res_ohm: 33; SizeX_mm: 1.6; SizeY_mm: 0.8; SizeZ_mm: 1; Value2: 0.1W; SizeArea_mm2: 1.28; AEC Qualified: N; VDC_V: 75V; AEC Category: Q200; SizeAreaWB_mm2: 4.68
U1 = CMP-0090171-1: 300-mA low-dropout (LDO) regulator with foldback current limit 5-SOT-23 -40 to 125; Manufacturer: Texas Instruments; SizeZ_mm: 1.45mm; Output Type: Fixed; Nominal Supply Current: 50uA; TJmax_C: +85°C; Max Supply Voltage: 5.5V; Standoff Height: 0mm; AEC Qualified: No; Accuracy Percentage: 1%; Output Voltage: 3.3V; Number Of Outputs: 1; Dropout Voltage: 460mV
U2 = CMP-0066190-1: Low-Drift, Low-Power, Dual-Output VREF and VREF/2 Voltage Reference, DDC0005A (SOT-23-T-5); Alternate PartNumber: REF2033AIDDCT; Alternate Manufacturer: Texas Instruments; SizeAreaWB_mm2: 14.82; U/M: EA; SizeZ_mm: 1.1; SizeX_mm: 2.8; SizeY_mm: 2.9; SizeArea_mm2: 8.12; CompType: IC
U3 = CMP-0079285-1: Delta-Sigma Modulator with Bipolar Input and Reference Output, D0008A (SOIC-8); Alternate PartNumber: AMC1035DR; Alternate Manufacturer: Texas Instruments; SizeAreaWB_mm2: 56.58; SizeZ_mm: 1.75; SizeX_mm: 4.9; SizeY_mm: 6.2; SizeArea_mm2: 30.38; CompType: IC; AEC Qualified: N; AEC Category: Q200
U4 = CMP-0096053-1: Manufacturer: Texas Instruments; Standoff Height: 0.1mm; SizeZ_mm: 2.65mm
U5 = CMP-0075943-2: Ultra-Low Power, Ultra-Small Size, 12-Bit, 1-MSPS, SAR ADC, RUG0008A (X2QFN-8); Manufacturer: Texas Instruments; SizeAreaWB_mm2: 6.25; SizeArea_mm2: 2.25; SizeZ_mm: 0.4; SizeY_mm: 1.5; CompType: IC; AEC Category: Q200; AEC Qualified: N
U6 = CMP-0051705-3: Single Schmitt-Trigger Buffer, DCK0005A, SMALL T&R; Manufacturer: Texas Instruments; Logic: True; Output Type: CMOS; VCC(Max)(V): 5.5; Schmitt Trigger: Yes; Rating: Catalog; Output Drive (IOL/IOH)(Max)(mA): 32/-32; Input Type: CMOS/TTL; ICC @ Nom Voltage(Max)(mA): 0.01; F @ Nom Voltage(Max)(Mhz): 150; Technology Family: LVC; VCC(Min)(V): 1.65; 3-State Output: No; Voltage(Nom)(V): 1.8,2.5,3.3,5; Bits(#): 1; Sub-Family: Non-Inverting Buffer/Driver; tpd @ Nom Voltage(Max)(ns): 11,6.5,5.5,5; AEC Category: Q200; AEC Qualified: N; CompType: IC; SizeAreaWB_mm2: 9.3; SizeArea_mm2: 4.2; SizeX_mm: 2.1; SizeY_mm: 2.0; SizeZ_mm: 1.1

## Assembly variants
TMCS1123: not fitted C8 C8 C10 C11 C11 C14 C19 C19 C21 C21 R7 R10 R10 R26 R27 R29 R29 R31 R31 R34 R34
